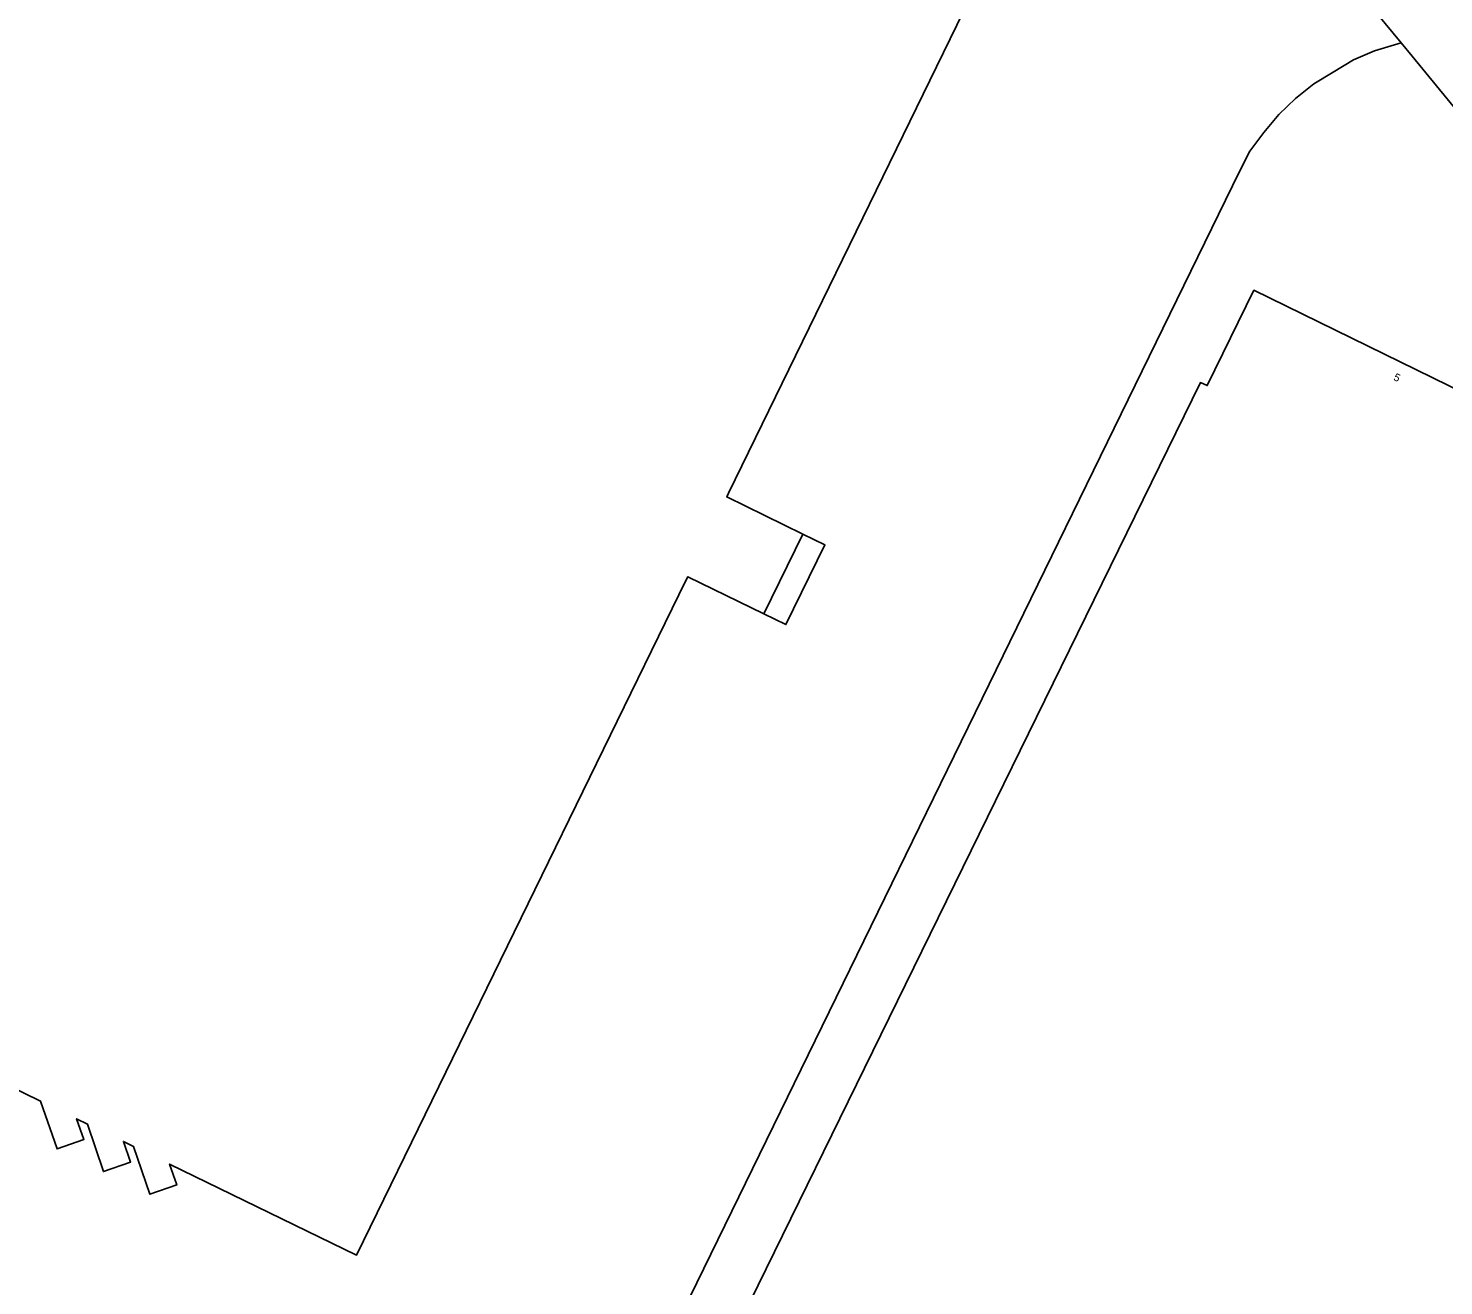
# Model space of a CAD drawing. Extents: x 156141 to 158132, y 385651 to 388399.
# Drawn here: x 156808.9 to 156991.7, y 386347.8 to 386510.1 of the extents above; entities that cross this region are included whole.
import ezdxf

# ---------------------------------------------------------------- set-up
doc = ezdxf.new("R2010")
doc.units = 0
for name, color, linetype in [('IMGEO_Erf', 7, 'Continuous'), ('IMGEO_Pand', 7, 'Continuous'), ('IMGEO_Pand_nummerreeks', 7, 'Continuous'), ('IMGEO_Pand_overbouw', 7, 'Continuous'), ('IMGEO_Rijbaan_lokaal_open', 7, 'Continuous'), ('IMGEO_Voetpad_op_trap', 7, 'Continuous')]:
    doc.layers.add(name, color=color, linetype=linetype)

msp = doc.modelspace()

# ---------------------------------------------------------------- linework, layer by layer
at = {"layer": 'IMGEO_Erf'}
msp.add_lwpolyline([(156986.18, 386508.22), (156982.74, 386507.19), (156980.02, 386506.02), (156977.41, 386504.45), (156974.9, 386502.92), (156972.53, 386501.02), (156970.4, 386498.96), (156968.44, 386496.63), (156966.64, 386494.22), (156965.31, 386491.61), (156877.29, 386311.4)], dxfattribs=at)
at = {"layer": 'IMGEO_Pand'}
for points in [[(156908.92, 386444.79), (156899.1, 386449.6), (156899.33, 386450.08), (156941.81, 386537.18), (156921.59, 386547.04), (156915.66, 386549.94), (156914.03, 386550.73), (156915.27, 386553.27), (156914.59, 386553.61), (156913.35, 386551.07), (156905.93, 386554.69), (156907.17, 386557.24), (156906.49, 386557.57), (156905.24, 386555.02), (156896.19, 386559.44), (156902.2, 386571.76), (156890.86, 386577.29), (156881.48, 386581.86), (156864.43, 386590.19), (156856.4, 386594.11)], [(156894.65, 386330.53), (156960.26, 386464.36), (156961.14, 386463.97), (156967.17, 386476.28), (157004.95, 386457.81)], [(156903.9, 386434.5), (156908.92, 386444.79)], [(156803.94, 386374.79), (156810.46, 386371.62), (156812.61, 386365.44), (156816.09, 386366.66), (156815.13, 386369.34), (156816.55, 386368.65), (156818.61, 386362.52), (156822.1, 386363.73), (156821.18, 386366.4), (156822.48, 386365.77), (156824.58, 386359.59), (156828.07, 386360.79), (156827.15, 386363.49), (156851.29, 386351.74), (156893.83, 386438.81), (156894.07, 386439.29), (156903.9, 386434.5)]]:
    msp.add_lwpolyline(points, dxfattribs=at)
at = {"layer": 'IMGEO_Pand_overbouw'}
msp.add_lwpolyline([(156911.77, 386443.41), (156908.92, 386444.79), (156903.9, 386434.5), (156906.74, 386433.12)], close=True, dxfattribs=at)
at = {"layer": 'IMGEO_Rijbaan_lokaal_open'}
for points in [[(156978.47, 386517.59), (156981.22, 386514.25), (156986.18, 386508.22)], [(156986.18, 386508.22), (156987.59, 386506.51), (156993.9, 386498.84)]]:
    msp.add_lwpolyline(points, dxfattribs=at)
at = {"layer": 'IMGEO_Voetpad_op_trap'}
msp.add_lwpolyline([(156908.92, 386444.79), (156911.77, 386443.41), (156906.74, 386433.12), (156903.9, 386434.5)], dxfattribs=at)

# ---------------------------------------------------------------- texts
at = {"layer": 'IMGEO_Pand_nummerreeks'}
msp.add_text('5', height=1, rotation=333.9476, dxfattribs=at).set_placement((156985.1, 386464.73))

doc.saveas('drawing.dxf')
